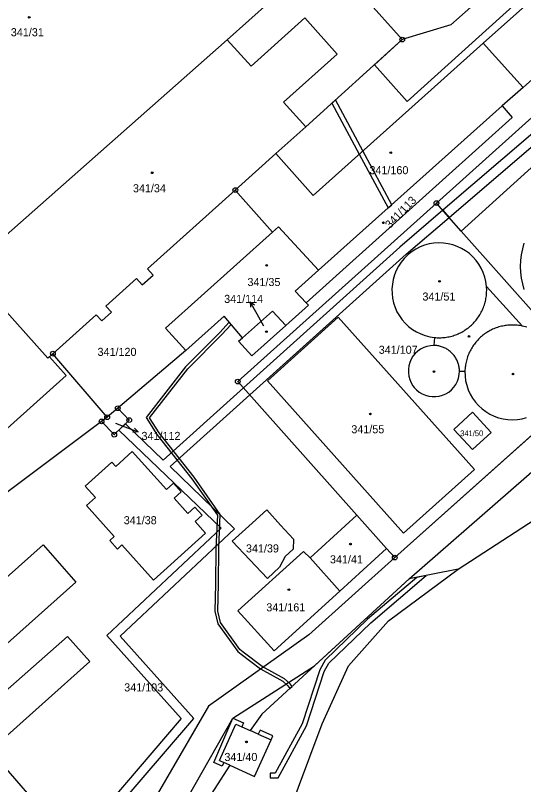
# Model space of a CAD drawing. Extents: x -562167 to -556918, y -1077891 to -1070763.
# Drawn here: x -557836.8 to -557729.6, y -1073189.3 to -1073027.1 of the extents above; entities that cross this region are included whole.
import ezdxf

# ---------------------------------------------------------------- set-up
doc = ezdxf.new("R2010")
doc.units = 0
for name, color, linetype in [('Hranice parcel', 7, 'Continuous'), ('Parcelní čísla', 7, 'Continuous'), ('Pop  PČ popisy', 7, 'Continuous'), ('Vnitřní kresba', 7, 'Continuous'), ('Věcná břemena k části', 7, 'Continuous'), ('Značky bodu BP', 7, 'Continuous'), ('Značky budov', 7, 'Continuous')]:
    doc.layers.add(name, color=color, linetype=linetype)

msp = doc.modelspace()

# ---------------------------------------------------------------- linework, layer by layer
at = {"layer": 'Hranice parcel'}
for p, q in [((-557755.21, -1073032.25), (-557787.25, -1072996.39)), ((-557710.82, -1073008.64), (-557738.1, -1073033)), ((-557702.53, -1073017.97), (-557729.72, -1073042.32)), ((-557846.84, -1073080.53), (-557792.11, -1073032.31)), ((-557775.57, -1073050.65), (-557755.21, -1073032.25)), ((-557747.98, -1073066.71), (-557710.77, -1073033.31)), ((-557738.1, -1073033), (-557729.72, -1073042.32)), ((-557742.74, -1073072.61), (-557705.68, -1073039.04)), ((-557729.72, -1073042.32), (-557734.13, -1073046.22)), ((-557734.13, -1073046.22), (-557772.88, -1073080.86)), ((-557781.87, -1073056.26), (-557775.57, -1073050.65)), ((-557790.42, -1073063.96), (-557781.87, -1073056.26)), ((-557782.58, -1073072.8), (-557790.42, -1073063.96)), ((-557789.9, -1073104.33), (-557747.98, -1073066.71)), ((-557742.74, -1073072.61), (-557747.98, -1073066.71)), ((-557714.86, -1073104), (-557742.74, -1073072.61)), ((-557729.85, -1073092.62), (-557737.41, -1073084.25)), ((-557748.41, -1073095.04), (-557748.54, -1073096.71)), ((-557829.63, -1073099.1), (-557828.9, -1073098.44)), ((-557817.46, -1073111.83), (-557828.9, -1073098.44)), ((-557800.85, -1073097.8), (-557815.22, -1073109.94)), ((-557743.12, -1073102.12), (-557741.97, -1073102.15)), ((-557764.76, -1073132.49), (-557789.9, -1073104.33)), ((-557714.86, -1073104), (-557756.78, -1073141.42)), ((-557815.22, -1073109.94), (-557817.46, -1073111.83)), ((-557817.46, -1073111.83), (-557818.64, -1073112.71)), ((-557774.63, -1073141.48), (-557764.76, -1073132.49)), ((-557758.52, -1073139.48), (-557764.76, -1073132.49)), ((-557776.03, -1073140.14), (-557774.63, -1073141.48)), ((-557758.52, -1073139.48), (-557768.39, -1073148.51)), ((-557756.78, -1073141.42), (-557758.52, -1073139.48)), ((-557774.63, -1073141.48), (-557768.39, -1073148.51)), ((-557768.39, -1073148.51), (-557782.21, -1073161.07))]:
    msp.add_line(p, q, dxfattribs=at)
for points in [[(-557823.21, -1072979.12), (-557783, -1073024.15), (-557792.11, -1073032.31)], [(-557792.11, -1073032.31), (-557787.09, -1073037.84), (-557775.78, -1073027.69), (-557768.96, -1073035.29), (-557780.27, -1073045.44), (-557775.57, -1073050.65)], [(-557738.1, -1073033), (-557749.08, -1073042.84), (-557773.98, -1073065.09), (-557781.87, -1073056.26)], [(-557734.13, -1073046.22), (-557732.02, -1073048.68), (-557775.47, -1073087.71)], [(-557828.9, -1073098.44), (-557819.76, -1073090.25), (-557818.61, -1073091.54), (-557816.57, -1073089.7), (-557817.71, -1073088.42), (-557811.24, -1073082.61), (-557810.05, -1073083.93), (-557807.78, -1073081.89), (-557808.96, -1073080.58), (-557790.42, -1073063.96)], [(-557782.58, -1073072.8), (-557805.13, -1073093.03), (-557800.85, -1073097.8)], [(-557772.88, -1073080.86), (-557781.29, -1073071.74), (-557782.58, -1073072.8)], [(-557737.41, -1073084.25), (-557737.54, -1073083.26), (-557737.78, -1073082.29), (-557738.1, -1073081.34), (-557738.53, -1073080.43), (-557739.04, -1073079.57), (-557739.63, -1073078.77), (-557740.3, -1073078.03), (-557741.04, -1073077.35), (-557741.84, -1073076.76), (-557742.7, -1073076.25), (-557743.61, -1073075.83), (-557744.55, -1073075.5), (-557745.53, -1073075.26), (-557746.52, -1073075.13), (-557747.52, -1073075.09), (-557748.51, -1073075.16), (-557749.5, -1073075.32), (-557750.47, -1073075.58), (-557751.4, -1073075.94), (-557752.3, -1073076.38), (-557753.14, -1073076.92), (-557753.93, -1073077.53), (-557754.1, -1073077.69), (-557754.81, -1073078.4), (-557755.44, -1073079.17), (-557755.99, -1073080.01), (-557756.45, -1073080.89), (-557756.83, -1073081.82), (-557757.11, -1073082.78), (-557757.29, -1073083.76), (-557757.37, -1073084.76), (-557757.35, -1073085.76), (-557757.24, -1073086.75), (-557757.02, -1073087.73), (-557756.71, -1073088.68), (-557756.31, -1073089.59), (-557755.81, -1073090.46), (-557755.23, -1073091.28), (-557754.58, -1073092.03), (-557753.85, -1073092.72), (-557753.05, -1073093.32), (-557752.2, -1073093.85), (-557751.31, -1073094.29), (-557750.37, -1073094.64), (-557749.4, -1073094.89), (-557748.41, -1073095.04)], [(-557730.24, -1073080.05), (-557730.19, -1073078.81), (-557730.04, -1073077.58), (-557729.79, -1073076.36), (-557729.45, -1073075.17)], [(-557829.63, -1073099.1), (-557829.96, -1073099.4), (-557846.84, -1073080.53)], [(-557775.47, -1073087.71), (-557777.79, -1073085.25), (-557772.88, -1073080.86)], [(-557729.45, -1073084.93), (-557729.79, -1073083.74), (-557730.04, -1073082.52), (-557730.19, -1073081.29), (-557730.24, -1073080.05)], [(-557775.47, -1073087.71), (-557774.99, -1073088.22), (-557779.76, -1073092.48)], [(-557788.88, -1073095.07), (-557792.78, -1073090.56), (-557800.85, -1073097.8)], [(-557788.88, -1073095.07), (-557782.59, -1073089.48), (-557779.76, -1073092.48)], [(-557783.64, -1073104.15), (-557754.9, -1073136.24), (-557739.98, -1073122.83), (-557768.71, -1073090.76), (-557783.64, -1073104.15)], [(-557779.76, -1073092.48), (-557786.96, -1073098.92), (-557789.72, -1073095.81), (-557788.88, -1073095.07)], [(-557728.89, -1073092.88), (-557729.85, -1073092.62)], [(-557748.54, -1073096.71), (-557749.27, -1073096.76), (-557749.99, -1073096.91), (-557750.68, -1073097.16), (-557751.34, -1073097.5), (-557751.94, -1073097.93), (-557752.47, -1073098.43), (-557752.94, -1073099), (-557753.32, -1073099.63), (-557753.61, -1073100.3), (-557753.81, -1073101.01), (-557753.91, -1073101.74), (-557753.91, -1073102.47), (-557753.81, -1073103.2), (-557753.61, -1073103.91), (-557753.32, -1073104.58), (-557752.94, -1073105.21), (-557752.69, -1073105.54), (-557752.19, -1073106.08), (-557751.61, -1073106.54), (-557750.98, -1073106.92), (-557750.31, -1073107.21), (-557749.6, -1073107.4), (-557748.87, -1073107.5), (-557748.14, -1073107.5), (-557747.41, -1073107.4), (-557746.7, -1073107.2), (-557746.03, -1073106.9), (-557745.4, -1073106.52), (-557744.83, -1073106.05), (-557744.33, -1073105.52), (-557743.91, -1073104.92), (-557743.57, -1073104.27), (-557743.32, -1073103.57), (-557743.17, -1073102.85), (-557743.12, -1073102.12)], [(-557857.07, -1073133.83), (-557858.59, -1073132.11), (-557826.1, -1073103.05), (-557829.63, -1073099.1)], [(-557741.97, -1073102.15), (-557741.94, -1073103.15), (-557741.82, -1073104.14), (-557741.59, -1073105.11), (-557741.27, -1073106.06), (-557740.85, -1073106.97), (-557740.35, -1073107.83), (-557739.76, -1073108.64), (-557739.1, -1073109.39), (-557738.36, -1073110.06), (-557737.56, -1073110.66), (-557736.7, -1073111.17), (-557735.8, -1073111.6), (-557734.86, -1073111.94), (-557733.89, -1073112.18), (-557732.9, -1073112.32), (-557731.9, -1073112.36), (-557730.9, -1073112.3), (-557729.92, -1073112.14), (-557728.95, -1073111.88)], [(-557815.22, -1073109.94), (-557812.79, -1073112.45), (-557815.97, -1073115.51), (-557818.64, -1073112.71)], [(-557736.46, -1073115.05), (-557740.37, -1073110.77), (-557744.33, -1073114.39), (-557740.4, -1073118.62), (-557736.46, -1073115.05)], [(-557818.64, -1073112.71), (-557852.73, -1073138.22), (-557868.31, -1073151.46)], [(-557743.42, -1073143.89), (-557721.96, -1073129.96), (-557671.2, -1073112.1)], [(-557804.94, -1073127.09), (-557803.45, -1073125.76), (-557801.85, -1073127.56), (-557803.34, -1073128.88), (-557800.43, -1073132.12), (-557798.94, -1073130.79), (-557797.4, -1073132.5), (-557798.89, -1073133.84), (-557796.7, -1073136.28), (-557807.66, -1073146.17), (-557814.34, -1073138.76), (-557815.3, -1073139.63), (-557816.91, -1073137.85), (-557815.95, -1073136.98), (-557821.83, -1073130.46), (-557819.94, -1073128.76), (-557822.07, -1073126.38), (-557816.5, -1073121.29), (-557815.61, -1073122.21), (-557812.15, -1073119.04), (-557810.86, -1073120.5), (-557804.94, -1073127.09)], [(-557783.8, -1073131.32), (-557780.89, -1073134.62), (-557778.16, -1073137.57), (-557778.24, -1073139.62), (-557779.93, -1073141.16), (-557781.08, -1073143.43), (-557783.65, -1073145.85), (-557791.06, -1073137.99), (-557787.6, -1073134.78), (-557783.8, -1073131.32)], [(-557824.08, -1073146.59), (-557843.83, -1073164.15), (-557838.95, -1073169.66), (-557825.8, -1073158.02), (-557821.14, -1073163.32), (-557841.27, -1073181.29), (-557857.7, -1073162.5), (-557830.99, -1073138.72), (-557824.08, -1073146.59)], [(-557782.21, -1073161.07), (-557789.88, -1073152.64), (-557776.03, -1073140.14)], [(-557743.42, -1073143.89), (-557753.77, -1073145.9), (-557784.82, -1073174.44), (-557787.26, -1073177.86)], [(-557779.66, -1073196.74), (-557772.11, -1073176.43), (-557766.56, -1073164.21), (-557758.13, -1073154.77), (-557743.42, -1073143.89)], [(-557791.57, -1073185.2), (-557792.87, -1073184.61), (-557793.22, -1073185.39), (-557794.94, -1073184.61), (-557790.91, -1073175.28), (-557788.66, -1073176.28), (-557789.02, -1073177.07), (-557787.26, -1073177.86)], [(-557791.57, -1073185.2), (-557786.38, -1073187.55), (-557782.88, -1073179.82), (-557782.53, -1073179.02), (-557785.2, -1073177.81), (-557785.57, -1073178.63), (-557787.26, -1073177.86)], [(-557791.57, -1073185.2), (-557798.84, -1073196.43), (-557800.39, -1073201.86)]]:
    msp.add_lwpolyline(points, dxfattribs=at)
at = {"layer": 'Pop  PČ popisy'}
for p, q in [((-557785.82, -1073090.14), (-557787.32, -1073087.54)), ((-557787.32, -1073087.54), (-557786.39, -1073088.16)), ((-557787.32, -1073087.54), (-557787.25, -1073088.66)), ((-557784.41, -1073092.63), (-557785.82, -1073090.14)), ((-557815.73, -1073113.1), (-557813.72, -1073113.86)), ((-557813.72, -1073113.86), (-557810.92, -1073114.94)), ((-557810.92, -1073114.94), (-557812.03, -1073115.04)), ((-557810.92, -1073114.94), (-557811.67, -1073114.11))]:
    msp.add_line(p, q, dxfattribs=at)
at = {"layer": 'Vnitřní kresba'}
for p, q in [((-557793.79, -1073184.19), (-557790.29, -1073176.53)), ((-557790.29, -1073176.53), (-557789.02, -1073177.07)), ((-557785.57, -1073178.63), (-557782.88, -1073179.82)), ((-557793.79, -1073184.19), (-557792.87, -1073184.61))]:
    msp.add_line(p, q, dxfattribs=at)
for points in [[(-557748.41, -1073095.04), (-557748.13, -1073095.06), (-557747.84, -1073095.08), (-557747.56, -1073095.09), (-557747.28, -1073095.09), (-557747, -1073095.08), (-557746.71, -1073095.06), (-557746.43, -1073095.04), (-557746.15, -1073095.01), (-557745.87, -1073094.97), (-557745.59, -1073094.92), (-557745.31, -1073094.86), (-557745.04, -1073094.8), (-557744.76, -1073094.73), (-557744.49, -1073094.65), (-557744.22, -1073094.56), (-557743.95, -1073094.47), (-557743.69, -1073094.37), (-557743.43, -1073094.26), (-557743.17, -1073094.14), (-557742.92, -1073094.02), (-557742.66, -1073093.89), (-557742.42, -1073093.75), (-557742.17, -1073093.6), (-557741.93, -1073093.45), (-557741.7, -1073093.29), (-557741.47, -1073093.13), (-557741.24, -1073092.96), (-557741.02, -1073092.78), (-557740.81, -1073092.6), (-557740.6, -1073092.41), (-557740.39, -1073092.21), (-557740.19, -1073092.01), (-557740, -1073091.8), (-557739.81, -1073091.59), (-557739.63, -1073091.38), (-557739.45, -1073091.15), (-557739.29, -1073090.93), (-557739.12, -1073090.69), (-557738.97, -1073090.46), (-557738.82, -1073090.22), (-557738.68, -1073089.97), (-557738.54, -1073089.72), (-557738.41, -1073089.47), (-557738.29, -1073089.22), (-557738.18, -1073088.96), (-557738.07, -1073088.69), (-557737.97, -1073088.43), (-557737.88, -1073088.16), (-557737.79, -1073087.89), (-557737.72, -1073087.62), (-557737.65, -1073087.34), (-557737.59, -1073087.07), (-557737.53, -1073086.79), (-557737.49, -1073086.51), (-557737.45, -1073086.23), (-557737.42, -1073085.95), (-557737.4, -1073085.67), (-557737.39, -1073085.38), (-557737.38, -1073085.1), (-557737.38, -1073084.82), (-557737.39, -1073084.53), (-557737.41, -1073084.25)], [(-557729.85, -1073092.62), (-557730.12, -1073092.56), (-557730.4, -1073092.52), (-557730.68, -1073092.48), (-557730.95, -1073092.45), (-557731.23, -1073092.42), (-557731.51, -1073092.41), (-557731.79, -1073092.4), (-557732.07, -1073092.4), (-557732.35, -1073092.4), (-557732.63, -1073092.42), (-557732.91, -1073092.44), (-557733.18, -1073092.47), (-557733.46, -1073092.51), (-557733.73, -1073092.55), (-557734.01, -1073092.61), (-557734.28, -1073092.67), (-557734.55, -1073092.74), (-557734.82, -1073092.81), (-557735.09, -1073092.9), (-557735.35, -1073092.99), (-557735.61, -1073093.08), (-557735.87, -1073093.19), (-557736.13, -1073093.3), (-557736.38, -1073093.42), (-557736.63, -1073093.55), (-557736.87, -1073093.68), (-557737.12, -1073093.82), (-557737.35, -1073093.97), (-557737.59, -1073094.12), (-557737.82, -1073094.28), (-557738.04, -1073094.45), (-557738.26, -1073094.62), (-557738.47, -1073094.8), (-557738.68, -1073094.99), (-557738.89, -1073095.18), (-557739.09, -1073095.37), (-557739.28, -1073095.57), (-557739.47, -1073095.78), (-557739.65, -1073095.99), (-557739.83, -1073096.21), (-557739.99, -1073096.43), (-557740.16, -1073096.66), (-557740.32, -1073096.89), (-557740.47, -1073097.12), (-557740.61, -1073097.36), (-557740.75, -1073097.61), (-557740.88, -1073097.85), (-557741, -1073098.1), (-557741.12, -1073098.36), (-557741.23, -1073098.62), (-557741.33, -1073098.88), (-557741.43, -1073099.14), (-557741.51, -1073099.4), (-557741.59, -1073099.67), (-557741.67, -1073099.94), (-557741.73, -1073100.21), (-557741.79, -1073100.49), (-557741.84, -1073100.76), (-557741.88, -1073101.04), (-557741.91, -1073101.31), (-557741.94, -1073101.59), (-557741.96, -1073101.87), (-557741.97, -1073102.15)], [(-557743.12, -1073102.12), (-557743.13, -1073101.91), (-557743.14, -1073101.71), (-557743.16, -1073101.5), (-557743.19, -1073101.3), (-557743.23, -1073101.09), (-557743.27, -1073100.89), (-557743.32, -1073100.69), (-557743.39, -1073100.49), (-557743.45, -1073100.3), (-557743.53, -1073100.1), (-557743.61, -1073099.91), (-557743.7, -1073099.73), (-557743.79, -1073099.54), (-557743.9, -1073099.36), (-557744.01, -1073099.19), (-557744.12, -1073099.02), (-557744.25, -1073098.85), (-557744.38, -1073098.69), (-557744.51, -1073098.53), (-557744.65, -1073098.38), (-557744.8, -1073098.23), (-557744.95, -1073098.09), (-557745.11, -1073097.96), (-557745.27, -1073097.83), (-557745.44, -1073097.71), (-557745.61, -1073097.59), (-557745.78, -1073097.48), (-557745.96, -1073097.38), (-557746.15, -1073097.28), (-557746.33, -1073097.2), (-557746.52, -1073097.11), (-557746.72, -1073097.04), (-557746.91, -1073096.97), (-557747.11, -1073096.91), (-557747.31, -1073096.86), (-557747.51, -1073096.82), (-557747.72, -1073096.78), (-557747.92, -1073096.75), (-557748.13, -1073096.73), (-557748.33, -1073096.72), (-557748.54, -1073096.71)]]:
    msp.add_lwpolyline(points, dxfattribs=at)
at = {"layer": 'Věcná břemena k části'}
for points in [[(-557690.15, -1072980.43), (-557716.05, -1073003.59), (-557744.96, -1073029.12), (-557755.21, -1073032.25), (-557761.07, -1073037.55), (-557754.16, -1073045.26), (-557710.91, -1073006.25), (-557695.95, -1072992.9), (-557689.96, -1072989.95), (-557685.5, -1072985.98)], [(-557745.31, -1073069.71), (-557707.3, -1073037.22), (-557673.26, -1073008.13), (-557654.71, -1073029.17), (-557650.48, -1073025.64), (-557651.81, -1073024.15), (-557654.49, -1073026.39), (-557673.08, -1073005.31), (-557708.64, -1073035.71), (-557746.65, -1073068.21)], [(-557764.26, -1073056.4), (-557758.18, -1073067.72), (-557757.42, -1073067.04), (-557763.49, -1073055.72), (-557769.27, -1073044.96), (-557770.03, -1073045.65)], [(-557787.39, -1073107.15), (-557754.38, -1073077.46), (-557745.31, -1073069.71), (-557746.65, -1073068.21), (-557755.72, -1073075.97), (-557788.71, -1073105.66), (-557805.62, -1073120.87), (-557813.57, -1073113.2), (-557815.01, -1073114.58), (-557793.4, -1073135.25), (-557817.5, -1073157.87), (-557801.84, -1073175.34), (-557828.67, -1073206.65), (-557827.35, -1073208.16), (-557799.19, -1073175.31), (-557814.7, -1073157.99), (-557790.59, -1073135.36), (-557804.18, -1073122.25)], [(-557791.69, -1073091.82), (-557793.7, -1073093.97), (-557800.92, -1073101.22), (-557809.26, -1073111.91), (-557806.95, -1073115.48), (-557799.61, -1073124.84), (-557794.19, -1073132.49), (-557794.51, -1073139.43), (-557794.58, -1073147.01), (-557794.72, -1073152.74), (-557794.08, -1073155.36), (-557789.88, -1073161.21), (-557789.17, -1073161.8), (-557785.08, -1073164.89), (-557780.38, -1073167.45), (-557779.31, -1073168.42), (-557778.89, -1073168.99), (-557778.45, -1073168.58), (-557778.87, -1073168.02), (-557780.02, -1073166.95), (-557784.76, -1073164.39), (-557788.79, -1073161.34), (-557789.44, -1073160.79), (-557793.52, -1073155.1), (-557794.12, -1073152.68), (-557793.98, -1073147.03), (-557793.91, -1073139.45), (-557793.59, -1073132.31), (-557799.13, -1073124.48), (-557806.47, -1073115.14), (-557808.52, -1073111.95), (-557800.46, -1073101.62), (-557793.26, -1073094.39), (-557791.29, -1073092.28)], [(-557771.7, -1073165.46), (-557770.66, -1073163.65), (-557761.82, -1073155.17), (-557750.16, -1073145.2), (-557752.14, -1073145.58), (-557762.5, -1073154.43), (-557771.46, -1073163.03), (-557772.62, -1073165.06), (-557776.34, -1073176.48), (-557782, -1073186.83), (-557783.09, -1073186.85), (-557783.07, -1073187.85), (-557781.4, -1073187.81), (-557775.42, -1073176.88)]]:
    msp.add_lwpolyline(points, close=True, dxfattribs=at)
for points in [[(-557643.47, -1073040.17), (-557677.52, -1073070.73), (-557714.86, -1073104), (-557756.78, -1073141.42), (-557774.88, -1073157.72), (-557796.11, -1073172.73), (-557811.17, -1073198.7)], [(-557807.13, -1073203.68), (-557790.91, -1073175.28), (-557773.71, -1073164.22), (-557753.77, -1073145.9), (-557710.86, -1073108.49), (-557673.53, -1073075.21), (-557637.61, -1073042.97)], [(-557823.97, -1073202.91), (-557845.97, -1073177.62), (-557857.7, -1073162.5), (-557868.31, -1073151.46), (-557872.45, -1073154.98), (-557872.27, -1073155.18), (-557870.89, -1073156.62), (-557868.98, -1073158.62), (-557868.42, -1073159.2), (-557867.04, -1073160.65), (-557864.71, -1073163.09), (-557859, -1073168.41), (-557853.62, -1073176.23), (-557850.51, -1073181.56), (-557848.03, -1073184.41), (-557846.71, -1073185.92), (-557831.22, -1073203.72)]]:
    msp.add_lwpolyline(points, dxfattribs=at)
at = {"layer": 'Značky bodu BP'}
for centre, radius in [((-557755.21, -1073032.25), 0.5), ((-557755.21, -1073032.25), 0.0303), ((-557790.42, -1073063.96), 0.5), ((-557790.42, -1073063.96), 0.0303), ((-557747.98, -1073066.71), 0.5), ((-557747.98, -1073066.71), 0.0303), ((-557828.9, -1073098.44), 0.5), ((-557828.9, -1073098.44), 0.0303), ((-557789.9, -1073104.33), 0.5), ((-557789.9, -1073104.33), 0.0303), ((-557815.22, -1073109.94), 0.5), ((-557815.22, -1073109.94), 0.0303), ((-557817.46, -1073111.83), 0.5), ((-557817.46, -1073111.83), 0.0303), ((-557818.64, -1073112.71), 0.5), ((-557818.64, -1073112.71), 0.0303), ((-557812.79, -1073112.45), 0.5), ((-557812.79, -1073112.45), 0.0303), ((-557815.97, -1073115.51), 0.5), ((-557815.97, -1073115.51), 0.0303), ((-557756.78, -1073141.42), 0.5), ((-557756.78, -1073141.42), 0.0303)]:
    msp.add_circle(centre, radius, dxfattribs=at)
at = {"layer": 'Značky budov'}
for centre in [(-557833.9, -1073027.56), (-557757.62, -1073056.09), (-557807.96, -1073060.31), (-557759.18, -1073070.86), (-557783.79, -1073079.83), (-557747.34, -1073083.19), (-557783.85, -1073093.8), (-557741.1, -1073094.82), (-557748.49, -1073102.2), (-557731.83, -1073102.74), (-557761.92, -1073111.14), (-557766.13, -1073138.58), (-557779.11, -1073148.19), (-557788.07, -1073180.26)]:
    msp.add_circle(centre, 0.175, dxfattribs=at)

# ---------------------------------------------------------------- texts
at = {"layer": 'Parcelní čísla'}
for s, height, p in [('341/31', 1.7, (-557837.78, -1073031.54)), ('341/160', 1.7, (-557762.12, -1073060.62)), ('341/34', 1.7, (-557812.02, -1073064.43)), ('341/35', 1.7, (-557787.86, -1073084.19)), ('341/51', 1.7, (-557750.94, -1073087.25)), ('341/114', 1.7, (-557792.77, -1073087.74)), ('341/120', 1.7, (-557819.49, -1073098.91)), ('341/107', 1.7, (-557760.16, -1073098.47)), ('341/55', 1.7, (-557765.94, -1073115.22)), ('341/112', 1.7, (-557810.21, -1073116.62)), ('341/50', 1.19, (-557742.97, -1073115.82)), ('341/38', 1.7, (-557813.96, -1073134.39)), ('341/39', 1.7, (-557788.17, -1073140.33)), ('341/41', 1.7, (-557770.45, -1073142.64)), ('341/161', 1.7, (-557783.88, -1073152.75)), ('341/103', 1.7, (-557813.86, -1073169.63)), ('341/40', 1.7, (-557792.72, -1073184.29))]:
    msp.add_text(s, height=height, dxfattribs=at).set_placement(p)
msp.add_text('341/113', height=1.7, rotation=46, dxfattribs=at).set_placement((-557757.79, -1073072.18))

doc.saveas('drawing.dxf')
